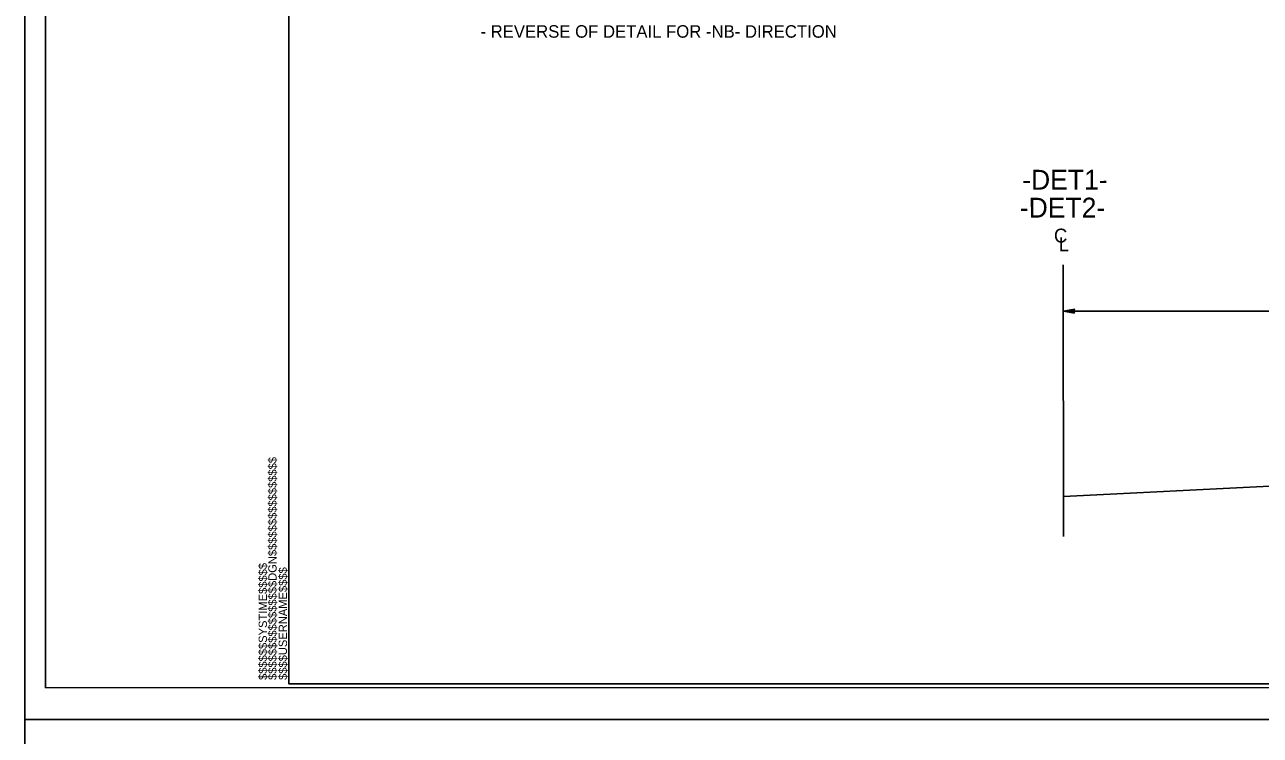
# Model space of a CAD drawing. Extents: x 2241081 to 2251104, y 658534 to 663427.
# Drawn here: x 2247636 to 2248415, y 659619 to 660067 of the extents above; entities that cross this region are included whole.
import ezdxf

# ---------------------------------------------------------------- set-up
doc = ezdxf.new("R2010")
doc.units = 0
for name, color, linetype in [('Old_Level_2', 7, 'Continuous'), ('Prop Dimension Text', 7, 'Continuous'), ('Sheet Cutting Line CELL', 7, 'Continuous'), ('Sheet Plan CELL', 7, 'Continuous'), ('Sheet Plot Border Inside CELL', 7, 'Continuous'), ('Sheet Plot Border Outside CELL', 7, 'Continuous'), ('Typical Terminator CELL', 7, 'Continuous'), ('Typical Text Centerline CELL', 7, 'Continuous'), ('Typical Text General CELL', 7, 'Continuous')]:
    doc.layers.add(name, color=color, linetype=linetype)

msp = doc.modelspace()

# ---------------------------------------------------------------- linework, layer by layer
at = {"layer": 'Old_Level_2'}
msp.add_line((2248424.93, 659776.46), (2248290.58, 659769.81), dxfattribs=at)
at = {"layer": 'Prop Dimension Text'}
msp.add_line((2248602.81, 659886.74), (2248290.51, 659886.55), dxfattribs=at)
at = {"layer": 'Sheet Cutting Line CELL'}
for p, q in [((2247635.51, 660724.27), (2247635.51, 659629.27)), ((2247635.51, 659629.27), (2247635.5, 658534.27)), ((2247635.51, 659629.27), (2249319.01, 659629.26)), ((2249319.01, 659629.26), (2247635.51, 659629.27))]:
    msp.add_line(p, q, dxfattribs=at)
at = {"layer": 'Sheet Plan CELL'}
msp.add_line((2247801.99, 659651.78), (2247801.99, 659651.78), dxfattribs=at)
for points in [[(2247801.99, 659651.78), (2247801.97, 660701.75), (2249101.96, 660701.79), (2249101.97, 660551.73), (2249302.01, 660551.71), (2249302.01, 659651.78)], [(2249302.03, 660701.78), (2247801.99, 660701.78), (2247801.99, 659651.78), (2249302.01, 659651.78)]]:
    msp.add_lwpolyline(points, close=True, dxfattribs=at)
at = {"layer": 'Sheet Plot Border Inside CELL'}
msp.add_lwpolyline([(2247648.51, 659649.27), (2249314.49, 659649.28), (2249314.51, 660704.26), (2247648.51, 660704.27)], close=True, dxfattribs=at)
at = {"layer": 'Sheet Plot Border Outside CELL'}
for points in [[(2247635.51, 659629.27), (2249319.01, 659629.26), (2249319.01, 660724.26), (2247635.51, 660724.27)], [(2247635.5, 658534.27), (2249319, 658534.26), (2249319.01, 659629.26), (2247635.51, 659629.27)]]:
    msp.add_lwpolyline(points, close=True, dxfattribs=at)
at = {"layer": 'Typical Terminator CELL'}
msp.add_lwpolyline([(2248297.54, 659885.34), (2248290.51, 659886.55), (2248297.57, 659887.8), (2248296.68, 659886.55)], close=True, dxfattribs=at)
at = {"layer": 'Typical Text Centerline CELL'}
msp.add_line((2248290.59, 659744.61), (2248290.49, 659915.86), dxfattribs=at)

# ---------------------------------------------------------------- texts
at = {"layer": 'Prop Dimension Text'}
for s, p in [('-DET1-', (2248264.57, 659963.21)), ('-DET2-', (2248263.07, 659945.62))]:
    msp.add_text(s, height=12.5, rotation=0.03489, dxfattribs=at).set_placement(p)
at = {"layer": 'Sheet Plan CELL'}
for s, p in [('$$$$$$$$$$$$$$$$DGN$$$$$$$$$$$$$$$$', (2247794.36, 659654.14)), ('$$$$$$SYSTIME$$$$$', (2247788.28, 659654.12)), ('$$$$USERNAME$$$$', (2247800.91, 659654.15))]:
    msp.add_text(s, height=5.25, rotation=89.99994, dxfattribs=at).set_placement(p)
at = {"layer": 'Typical Text Centerline CELL'}
for s, rotation, p in [('C', 0.03489, (2248284.56, 659929.88)), ('L', 359.98179, (2248287.59, 659924.38))]:
    msp.add_text(s, height=8.76, rotation=rotation, dxfattribs=at).set_placement(p)
at = {"layer": 'Typical Text General CELL'}
msp.add_text('- REVERSE OF DETAIL FOR -NB- DIRECTION', height=7.8775, rotation=359.99993, dxfattribs=at).set_placement((2247922.9, 660059.01))

doc.saveas('drawing.dxf')
